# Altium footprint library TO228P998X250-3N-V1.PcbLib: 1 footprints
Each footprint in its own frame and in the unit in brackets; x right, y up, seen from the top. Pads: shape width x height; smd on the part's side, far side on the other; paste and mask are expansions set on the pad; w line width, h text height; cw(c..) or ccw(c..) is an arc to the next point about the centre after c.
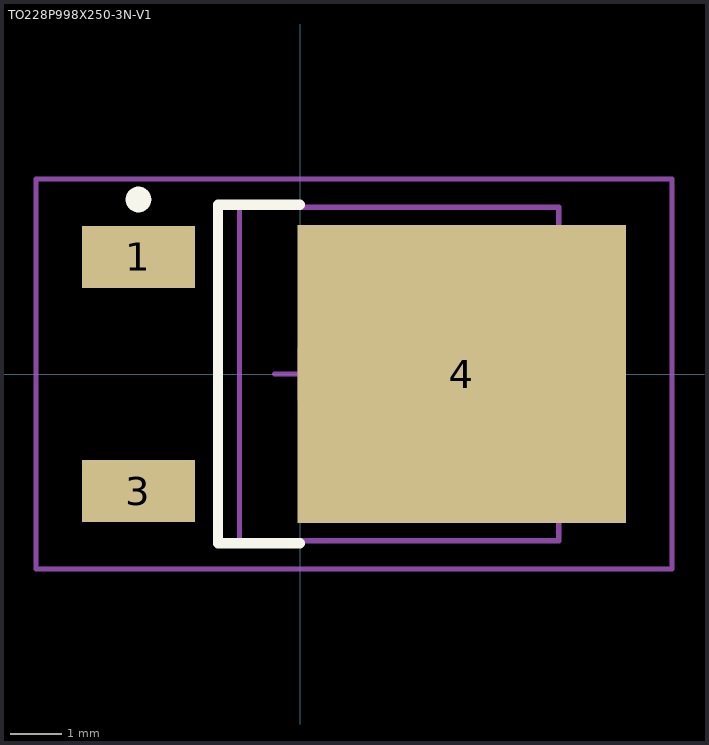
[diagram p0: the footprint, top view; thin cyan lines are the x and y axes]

## TO228P998X250-3N-V1 [mm] "TO,2.28mm pitch;2 pin,9.98mm L X 6.12mm W X 2.50mm H body"
height 2.5
pads (3):
  rect 2.2x1.2 smd paste+0 mask+0: 1(-3.15,2.28) 3(-3.15,-2.28)
  rect 6.4x5.8 smd paste+0 mask+0: 4(3.15,0)
Top Overlay:
  circle w0.25: c-3.15,3.4 r0.125
  lines w0.2: 0,-3.3 -1.6,-3.3 -1.6,3.3 0,3.3
M3 (ASY_Text_Top):
  text ".DESIGNATOR" at 0,0 h1.2
M13 (CMP_Body_OTL_Top):
  lines w0.1: -1.18,-3.25 -1.18,3.25 5.04,3.25 5.04,-3.25 -1.18,-3.25
M15 (CMP_Courtyard_Top):
  lines w0.1: -0.5,0 0.5,0 ; 0,-0.5 0,0.5 ; -5.15,-3.8 -5.15,3.8 7.25,3.8 7.25,-3.8 -5.15,-3.8
3D body "PG-TO252-3-313.stp": height 2.36, standoff 0, extent -3.94,-3.25 6.04,3.25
